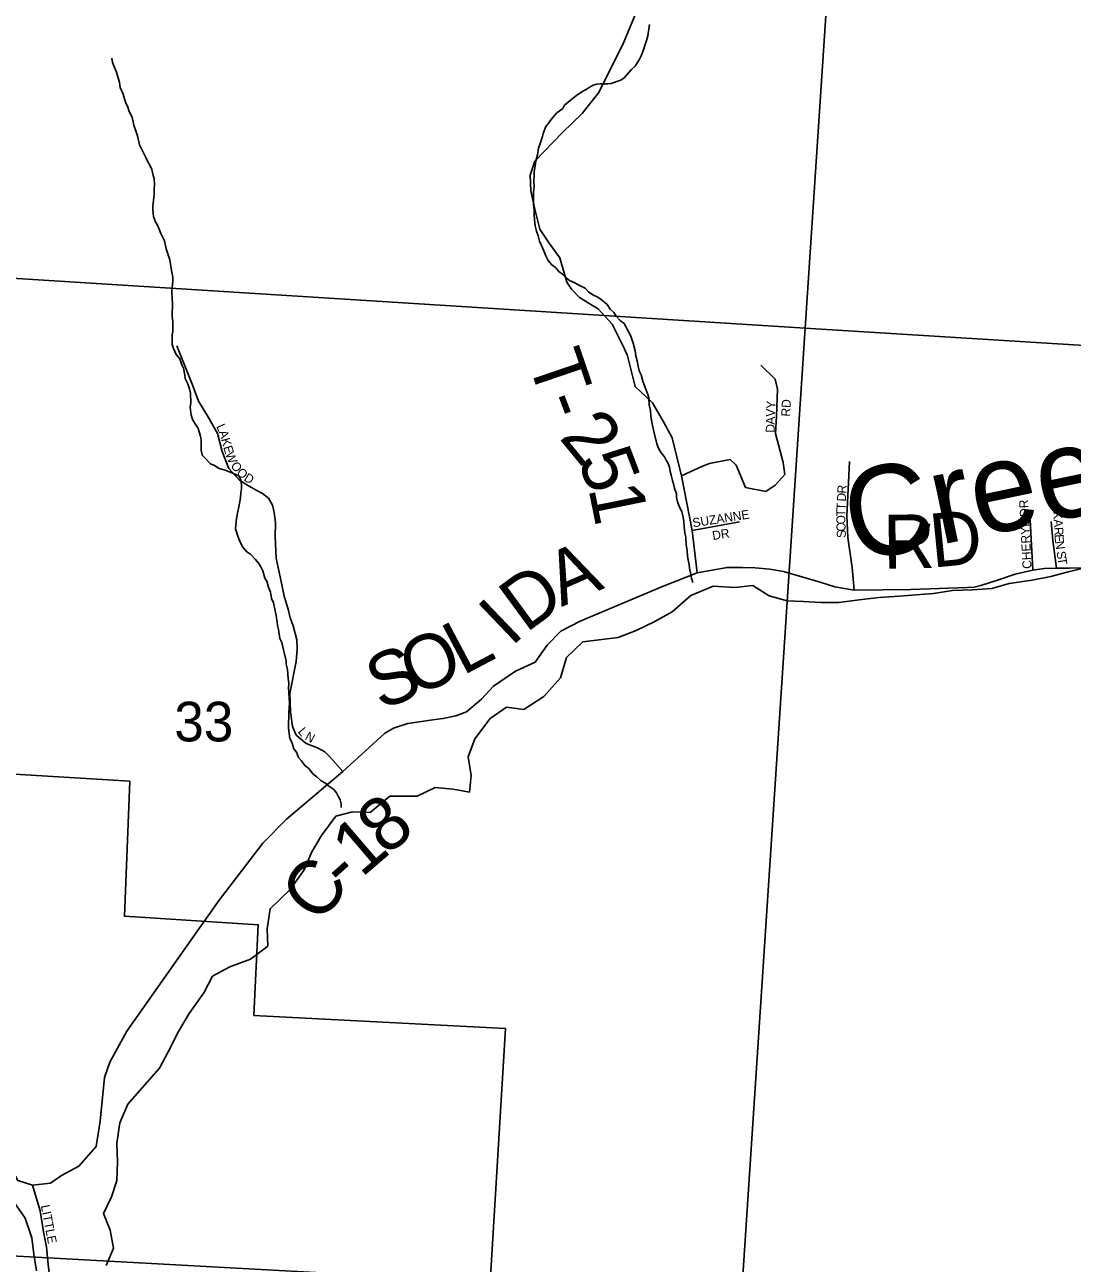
# Model space of a CAD drawing. Extents: x 1949938.81 to 1949945.61, y 152207.65 to 152214.09.
# Drawn here: x 1949941.599 to 1949942.704, y 152209.158 to 152210.465 of the extents above; entities that cross this region are included whole.
import ezdxf

# ---------------------------------------------------------------- set-up
doc = ezdxf.new("R2010")
doc.units = 0
for name, color, linetype in [('GM_X_City_Street', 7, 'Continuous'), ('GM_X_City_Street_Text', 7, 'Continuous'), ('GM_X_Corporation', 7, 'Continuous'), ('GM_X_County_Road', 7, 'Continuous'), ('GM_X_County_Road_Text', 7, 'Continuous'), ('GM_X_Minor_River', 7, 'Continuous'), ('GM_X_Minor_River_Text', 7, 'Continuous'), ('GM_X_Section', 7, 'Continuous'), ('GM_X_Section_Text', 7, 'Continuous'), ('GM_X_Township_Road', 7, 'Continuous'), ('GM_X_Township_Road_Text', 7, 'Continuous'), ('GM_X_Township_Subdivision', 7, 'Continuous'), ('GM_X_Township_Subdivision_Text', 7, 'Continuous')]:
    doc.layers.add(name, color=color, linetype=linetype)

msp = doc.modelspace()

# ---------------------------------------------------------------- linework, layer by layer
at = {"layer": 'GM_X_City_Street'}
for points in [[(1949941.4126, 152209.4825), (1949941.4273, 152209.4684), (1949941.4548, 152209.436), (1949941.4824, 152209.4065), (1949941.4928, 152209.3941), (1949941.4976, 152209.3871), (1949941.5005, 152209.3722), (1949941.5121, 152209.3585), (1949941.528, 152209.3455), (1949941.544, 152209.3266), (1949941.5648, 152209.2665), (1949941.5827, 152209.2632), (1949941.592, 152209.2455), (1949941.6075, 152209.2407), (1949941.6263, 152209.2428), (1949941.6379, 152209.251), (1949941.6564, 152209.2608), (1949941.6746, 152209.2817), (1949941.6788, 152209.3083), (1949941.6833, 152209.3542), (1949941.689, 152209.3706), (1949941.7068, 152209.4032), (1949941.7925, 152209.5244), (1949941.7945, 152209.5273)], [(1949941.6075, 152209.2407), (1949941.6156, 152209.2137), (1949941.6192, 152209.1915), (1949941.6221, 152209.1757), (1949941.6235, 152209.1607), (1949941.6257, 152209.142)]]:
    msp.add_lwpolyline(points, dxfattribs=at)
at = {"layer": 'GM_X_Corporation'}
msp.add_lwpolyline([(1949941.299, 152209.692), (1949941.7101, 152209.6669), (1949941.7046, 152209.5244), (1949941.8455, 152209.5155), (1949941.8409, 152209.4198), (1949942.1062, 152209.4059), (1949942.0896, 152209.1325)], dxfattribs=at)
at = {"layer": 'GM_X_County_Road'}
for points in [[(1949941.7945, 152209.5273), (1949941.8034, 152209.54), (1949941.8504, 152209.6014), (1949941.8754, 152209.627), (1949941.9347, 152209.6773), (1949941.9626, 152209.7025), (1949941.9788, 152209.7171), (1949941.988, 152209.723), (1949942.0032, 152209.7279), (1949942.0296, 152209.7315), (1949942.0403, 152209.733), (1949942.0537, 152209.7358), (1949942.0651, 152209.74), (1949942.0808, 152209.7534), (1949942.0936, 152209.7671), (1949942.1167, 152209.7831), (1949942.1376, 152209.7926), (1949942.1501, 152209.8104), (1949942.1645, 152209.8252), (1949942.1849, 152209.8359), (1949942.2719, 152209.8722), (1949942.3083, 152209.8869)], [(1949942.3083, 152209.8869), (1949942.3401, 152209.8924), (1949942.3561, 152209.8924), (1949942.3695, 152209.8921), (1949942.385, 152209.8906), (1949942.3995, 152209.888), (1949942.4381, 152209.877), (1949942.4536, 152209.8718), (1949942.474, 152209.8685), (1949942.5335, 152209.8691), (1949942.5934, 152209.8712), (1949942.6003, 152209.8716), (1949942.6073, 152209.8735), (1949942.6259, 152209.8795), (1949942.6437, 152209.8853), (1949942.6623, 152209.8896), (1949942.6747, 152209.8912), (1949942.6871, 152209.8918), (1949942.701, 152209.8916), (1949942.7151, 152209.8919)]]:
    msp.add_lwpolyline(points, dxfattribs=at)
at = {"layer": 'GM_X_Minor_River'}
for points in [[(1949942.1685, 152210.3801), (1949942.1743, 152210.385), (1949942.1812, 152210.3902), (1949942.1877, 152210.395), (1949942.1912, 152210.3965), (1949942.1946, 152210.3987), (1949942.1988, 152210.4013), (1949942.2022, 152210.4024), (1949942.2064, 152210.4027), (1949942.214, 152210.4025), (1949942.2178, 152210.4029), (1949942.2235, 152210.405), (1949942.2277, 152210.4065), (1949942.2315, 152210.4091), (1949942.2392, 152210.4177), (1949942.2431, 152210.4211), (1949942.2474, 152210.4286), (1949942.2493, 152210.432), (1949942.2517, 152210.4384), (1949942.2533, 152210.4429), (1949942.2553, 152210.4494), (1949942.2562, 152210.4532), (1949942.2579, 152210.4653)], [(1949941.7545, 152210.184), (1949941.7554, 152210.1943), (1949941.7555, 152210.1988), (1949941.7541, 152210.2057), (1949941.7524, 152210.2171), (1949941.751, 152210.2213), (1949941.7485, 152210.2286), (1949941.7467, 152210.237), (1949941.7427, 152210.2447), (1949941.7412, 152210.2493), (1949941.7394, 152210.2535), (1949941.7372, 152210.2569), (1949941.735, 152210.2627), (1949941.7344, 152210.2692), (1949941.7345, 152210.2737), (1949941.7358, 152210.2859), (1949941.7359, 152210.2923), (1949941.736, 152210.2958), (1949941.7357, 152210.3026), (1949941.7347, 152210.306), (1949941.7332, 152210.3122), (1949941.7307, 152210.3175), (1949941.7289, 152210.321), (1949941.727, 152210.3248), (1949941.7248, 152210.329), (1949941.7204, 152210.3382), (1949941.7183, 152210.3478), (1949941.7169, 152210.352), (1949941.7144, 152210.3589), (1949941.7126, 152210.3676), (1949941.7093, 152210.3734), (1949941.7079, 152210.378), (1949941.7057, 152210.3834), (1949941.7032, 152210.3918), (1949941.6999, 152210.3987), (1949941.6992, 152210.404), (1949941.696, 152210.4151), (1949941.6917, 152210.425), (1949941.691, 152210.4296)], [(1949942.3037, 152209.8766), (1949942.3022, 152209.8812), (1949942.3015, 152209.885), (1949942.3001, 152209.8915), (1949942.2998, 152209.8953), (1949942.2988, 152209.9003), (1949942.2981, 152209.9045), (1949942.2978, 152209.9102), (1949942.2968, 152209.9163), (1949942.2965, 152209.9243), (1949942.2955, 152209.9289), (1949942.2948, 152209.935), (1949942.2942, 152209.9414), (1949942.2932, 152209.9468), (1949942.2921, 152209.951), (1949942.2892, 152209.9571), (1949942.2877, 152209.9617), (1949942.2867, 152209.9663), (1949942.2864, 152209.9701), (1949942.2846, 152209.9762), (1949942.2835, 152209.9808), (1949942.2824, 152209.9842), (1949942.281, 152209.9899), (1949942.28, 152209.9938), (1949942.2793, 152209.9983), (1949942.2778, 152210.0022), (1949942.2756, 152210.0056), (1949942.2738, 152210.0091), (1949942.2705, 152210.0133), (1949942.2675, 152210.0183), (1949942.2657, 152210.0229), (1949942.2629, 152210.0344), (1949942.2611, 152210.042), (1949942.2601, 152210.0477), (1949942.2594, 152210.0523), (1949942.2591, 152210.058), (1949942.2577, 152210.0641), (1949942.2574, 152210.0713), (1949942.2564, 152210.0748), (1949942.2542, 152210.0805), (1949942.2524, 152210.0851), (1949942.2509, 152210.0889), (1949942.2492, 152210.0958), (1949942.2473, 152210.0997), (1949942.2459, 152210.1065), (1949942.2449, 152210.1103), (1949942.2435, 152210.1157), (1949942.2428, 152210.121), (1949942.2407, 152210.129), (1949942.2385, 152210.1363), (1949942.2352, 152210.1424), (1949942.2334, 152210.1459), (1949942.2312, 152210.1497), (1949942.2274, 152210.1525), (1949942.223, 152210.1575), (1949942.2204, 152210.1613), (1949942.2167, 152210.1648), (1949942.2133, 152210.1698), (1949942.207, 152210.1752), (1949942.2036, 152210.1776), (1949942.1984, 152210.18), (1949942.1939, 152210.1831), (1949942.1901, 152210.1869), (1949942.1834, 152210.1901), (1949942.1793, 152210.1928), (1949942.1736, 152210.1952), (1949942.1703, 152210.1979), (1949942.1665, 152210.2018), (1949942.1624, 152210.2045), (1949942.1591, 152210.2088), (1949942.155, 152210.2115), (1949942.1513, 152210.2161), (1949942.1487, 152210.2211), (1949942.1472, 152210.2246), (1949942.1454, 152210.2295), (1949942.1422, 152210.2368), (1949942.1407, 152210.2422), (1949942.1389, 152210.2471), (1949942.1375, 152210.2529), (1949942.1369, 152210.259), (1949942.1366, 152210.265), (1949942.1363, 152210.2689), (1949942.1356, 152210.2757), (1949942.1359, 152210.2883), (1949942.1363, 152210.2939), (1949942.1361, 152210.3008), (1949942.1365, 152210.3057), (1949942.1366, 152210.3103), (1949942.1375, 152210.3156), (1949942.1383, 152210.3213), (1949942.14, 152210.3277), (1949942.1412, 152210.3346), (1949942.1424, 152210.3387), (1949942.1452, 152210.347), (1949942.146, 152210.3504), (1949942.1488, 152210.3576), (1949942.1515, 152210.361), (1949942.1554, 152210.3663), (1949942.1604, 152210.3719), (1949942.1666, 152210.3767), (1949942.1685, 152210.3801)], [(1949941.9328, 152209.6392), (1949941.9329, 152209.643), (1949941.9319, 152209.6472), (1949941.93, 152209.6506), (1949941.9282, 152209.6545), (1949941.9252, 152209.658), (1949941.9211, 152209.6611), (1949941.9163, 152209.6649), (1949941.9117, 152209.6673), (1949941.9073, 152209.6716), (1949941.9035, 152209.6743), (1949941.8987, 152209.6804), (1949941.895, 152209.6832), (1949941.8909, 152209.6886), (1949941.8879, 152209.692), (1949941.8858, 152209.6974), (1949941.8832, 152209.7012), (1949941.881, 152209.7081), (1949941.8788, 152209.712), (1949941.8775, 152209.723), (1949941.8778, 152209.7397), (1949941.8782, 152209.7435), (1949941.8783, 152209.75), (1949941.878, 152209.7538), (1949941.8778, 152209.761), (1949941.8775, 152209.7652), (1949941.8776, 152209.7705), (1949941.8769, 152209.7751), (1949941.8763, 152209.7846), (1949941.8749, 152209.7903), (1949941.8749, 152209.7938), (1949941.8732, 152209.8014), (1949941.8721, 152209.8056), (1949941.8704, 152209.8132), (1949941.8682, 152209.8174), (1949941.8668, 152209.827), (1949941.8657, 152209.8312), (1949941.8654, 152209.8346), (1949941.8644, 152209.8418), (1949941.8634, 152209.8468), (1949941.8616, 152209.8552), (1949941.8594, 152209.8598), (1949941.8584, 152209.8663), (1949941.8562, 152209.8716), (1949941.8544, 152209.8778), (1949941.8526, 152209.8812), (1949941.8505, 152209.8888), (1949941.8483, 152209.8931), (1949941.8461, 152209.8965), (1949941.8424, 152209.9011), (1949941.8375, 152209.9066), (1949941.8334, 152209.9089), (1949941.8293, 152209.9139), (1949941.826, 152209.9197), (1949941.8235, 152209.9266), (1949941.8217, 152209.9331), (1949941.8218, 152209.9369), (1949941.8226, 152209.9441), (1949941.8239, 152209.9513), (1949941.8251, 152209.9562), (1949941.8256, 152209.96), (1949941.8268, 152209.966), (1949941.8273, 152209.971), (1949941.8277, 152209.9755), (1949941.8278, 152209.9801), (1949941.8271, 152209.9847), (1949941.8249, 152209.9889), (1949941.8178, 152209.9924), (1949941.8107, 152209.9952), (1949941.8042, 152209.9968), (1949941.7994, 152210), (1949941.7952, 152210.0019), (1949941.7897, 152210.0077), (1949941.7863, 152210.0108), (1949941.7853, 152210.0162), (1949941.7855, 152210.0268), (1949941.7848, 152210.031), (1949941.7823, 152210.039), (1949941.7797, 152210.0429), (1949941.7764, 152210.0479), (1949941.7749, 152210.0532), (1949941.7739, 152210.0616), (1949941.7744, 152210.0662), (1949941.7742, 152210.0764), (1949941.7731, 152210.0807), (1949941.7713, 152210.086), (1949941.7684, 152210.0918), (1949941.7681, 152210.0952), (1949941.7667, 152210.1028), (1949941.7649, 152210.1063), (1949941.7627, 152210.1124), (1949941.759, 152210.117), (1949941.7561, 152210.1235), (1949941.7546, 152210.1277), (1949941.7548, 152210.1376), (1949941.7553, 152210.1422), (1949941.7554, 152210.1517), (1949941.7548, 152210.1574), (1949941.755, 152210.1711), (1949941.7547, 152210.1756), (1949941.7545, 152210.184)], [(1949941.6971, 152209.2655), (1949941.6965, 152209.2852), (1949941.6996, 152209.3065), (1949941.708, 152209.3262), (1949941.7232, 152209.3436), (1949941.7415, 152209.3641), (1949941.7506, 152209.3815), (1949941.7613, 152209.4028), (1949941.7728, 152209.4217), (1949941.788, 152209.4437), (1949941.7972, 152209.4612), (1949941.8154, 152209.471), (1949941.8374, 152209.4793), (1949941.8556, 152209.4929), (1949941.8549, 152209.5111), (1949941.858, 152209.5324), (1949941.8793, 152209.5528), (1949941.8938, 152209.5733), (1949941.9022, 152209.5923), (1949941.9121, 152209.6097), (1949941.9274, 152209.6302), (1949941.9448, 152209.6347), (1949941.9637, 152209.6338), (1949941.9843, 152209.6512), (1949942.013, 152209.6511), (1949942.032, 152209.6602), (1949942.0509, 152209.6586), (1949942.0684, 152209.6555), (1949942.0699, 152209.673), (1949942.067, 152209.6928), (1949942.0739, 152209.7117), (1949942.0899, 152209.733), (1949942.1073, 152209.7451), (1949942.1255, 152209.7427), (1949942.1468, 152209.7563), (1949942.1643, 152209.776), (1949942.1704, 152209.7973), (1949942.1879, 152209.8139), (1949942.225, 152209.8184), (1949942.244, 152209.8259), (1949942.263, 152209.835), (1949942.282, 152209.8455), (1949942.3017, 152209.8629), (1949942.3252, 152209.8727), (1949942.348, 152209.8711), (1949942.3669, 152209.8733), (1949942.3843, 152209.8626), (1949942.4032, 152209.8573), (1949942.4206, 152209.8564), (1949942.4388, 152209.8556), (1949942.4577, 152209.8555), (1949942.482, 152209.8585), (1949942.5002, 152209.8607), (1949942.5214, 152209.8621), (1949942.5577, 152209.8651), (1949942.5774, 152209.868), (1949942.5987, 152209.8687), (1949942.6191, 152209.8701), (1949942.6373, 152209.8754), (1949942.6616, 152209.8791), (1949942.6813, 152209.8828), (1949942.701, 152209.8881), (1949942.723, 152209.8933)], [(1949941.6853, 152209.1561), (1949941.693, 152209.1743), (1949941.6893, 152209.1933), (1949941.6825, 152209.2108), (1949941.6909, 152209.2283), (1949941.6963, 152209.2457), (1949941.6971, 152209.2655)], [(1949941.5879, 152209.2233), (1949941.5999, 152209.2058), (1949941.6067, 152209.1852), (1949941.6089, 152209.1678), (1949941.6118, 152209.1503)]]:
    msp.add_lwpolyline(points, dxfattribs=at)
at = {"layer": 'GM_X_Section'}
for points in [[(1949942.4891, 152211.1555), (1949942.4221, 152210.1447), (1949941.3344, 152210.2133), (1949941.3926, 152211.2226)], [(1949943.6063, 152211.0859), (1949943.5439, 152210.0754), (1949942.4221, 152210.1447), (1949942.4891, 152211.1555)], [(1949941.3344, 152210.2133), (1949942.4221, 152210.1447), (1949942.3551, 152209.1241), (1949941.2772, 152209.1831)], [(1949942.4221, 152210.1447), (1949943.5439, 152210.0754), (1949943.4815, 152209.0627), (1949942.3551, 152209.1241)]]:
    msp.add_lwpolyline(points, close=True, dxfattribs=at)
at = {"layer": 'GM_X_Township_Road'}
for points in [[(1949942.2006, 152210.1673), (1949942.1981, 152210.1688), (1949942.1842, 152210.1772), (1949942.1759, 152210.1859), (1949942.1709, 152210.1935), (1949942.1637, 152210.219), (1949942.1524, 152210.2346), (1949942.1425, 152210.2494), (1949942.1372, 152210.2703), (1949942.1331, 152210.2897), (1949942.1323, 152210.3064), (1949942.1372, 152210.3209), (1949942.1664, 152210.3512), (1949942.1869, 152210.3714), (1949942.2043, 152210.393), (1949942.23, 152210.444), (1949942.2516, 152210.4968), (1949942.2607, 152210.515), (1949942.2657, 152210.5485), (1949942.2814, 152210.6236)], [(1949942.2329, 152210.1204), (1949942.2316, 152210.1231), (1949942.2187, 152210.149), (1949942.2039, 152210.1654), (1949942.2006, 152210.1673)], [(1949942.2774, 152210.0375), (1949942.2727, 152210.0462), (1949942.2613, 152210.066), (1949942.2429, 152210.0833), (1949942.2346, 152210.1171), (1949942.2329, 152210.1204)], [(1949942.3083, 152209.8869), (1949942.303, 152209.9314), (1949942.2919, 152209.9889), (1949942.2819, 152210.0291), (1949942.2774, 152210.0375)]]:
    msp.add_lwpolyline(points, dxfattribs=at)
at = {"layer": 'GM_X_Township_Subdivision'}
for points in [[(1949941.8734, 152209.8601), (1949941.8732, 152209.8605), (1949941.8696, 152209.8777), (1949941.8644, 152209.9021), (1949941.8633, 152209.9246), (1949941.8638, 152209.9397), (1949941.8623, 152209.9504), (1949941.8607, 152209.958), (1949941.8562, 152209.9656), (1949941.8501, 152209.9705), (1949941.844, 152209.9735), (1949941.8353, 152209.9785), (1949941.8258, 152209.9846), (1949941.8144, 152209.9967), (1949941.8076, 152210.0146), (1949941.8026, 152210.0336), (1949941.792, 152210.0522), (1949941.7824, 152210.068), (1949941.7766, 152210.0841), (1949941.7598, 152210.1262)], [(1949942.325, 152210.0028), (1949942.3376, 152210.0054), (1949942.3433, 152210.0063), (1949942.3494, 152210.0002), (1949942.3593, 152209.9767), (1949942.3808, 152209.9724), (1949942.3907, 152209.9791), (1949942.4007, 152209.9905), (1949942.3989, 152210.003), (1949942.3911, 152210.0339), (1949942.392, 152210.0521), (1949942.3929, 152210.0806), (1949942.3907, 152210.0909), (1949942.3753, 152210.1059)], [(1949942.2919, 152209.9889), (1949942.3138, 152209.9991), (1949942.3215, 152210.0021), (1949942.325, 152210.0028)], [(1949942.474, 152209.8685), (1949942.4719, 152209.8924), (1949942.4673, 152209.9239), (1949942.4661, 152209.9471), (1949942.4678, 152209.9821), (1949942.4691, 152210.0041)], [(1949942.303, 152209.9314), (1949942.353, 152209.9406)], [(1949942.6623, 152209.8896), (1949942.6593, 152209.9428)], [(1949942.6871, 152209.8918), (1949942.6835, 152209.9209), (1949942.6816, 152209.9409)], [(1949941.9347, 152209.6773), (1949941.9211, 152209.6927), (1949941.9157, 152209.6979), (1949941.908, 152209.702), (1949941.8962, 152209.7068), (1949941.8856, 152209.7156), (1949941.8815, 152209.7248), (1949941.8795, 152209.74), (1949941.879, 152209.7595), (1949941.8854, 152209.7933), (1949941.8867, 152209.8061), (1949941.8862, 152209.8159), (1949941.8824, 152209.8307), (1949941.8791, 152209.8392), (1949941.8774, 152209.847), (1949941.8734, 152209.8601)]]:
    msp.add_lwpolyline(points, dxfattribs=at)

# ---------------------------------------------------------------- texts
at = {"layer": 'GM_X_City_Street_Text'}
msp.add_text('LITTLE', height=0.00947, rotation=280.8384, dxfattribs=at).set_placement((1949941.6162, 152209.2191))
at = {"layer": 'GM_X_County_Road_Text'}
for s, rotation, p in [('D', 5.6492, (1949942.5564, 152209.8921)), ('R', 0.8443, (1949942.5047, 152209.8911)), ('A', 23.6227, (1949942.1652, 152209.8506)), ('D', 36.2524, (1949942.1277, 152209.8227)), ('I', 43.7313, (1949942.1124, 152209.8078)), ('O', 23.0796, (1949942.0103, 152209.7561)), ('L', 27.9642, (1949942.061, 152209.7779)), ('S', 22.9889, (1949941.9749, 152209.7411)), ('8', 40.3495, (1949941.9808, 152209.5872)), ('1', 40.6202, (1949941.9543, 152209.5644)), ('C', 50.205, (1949941.9088, 152209.5148)), ('-', 41.8567, (1949941.9371, 152209.5491))]:
    msp.add_text(s, height=0.0568, rotation=rotation, dxfattribs=at).set_placement(p)
at = {"layer": 'GM_X_Minor_River_Text'}
msp.add_text('Creek', height=0.0947, rotation=11.8017, dxfattribs=at).set_placement((1949942.4743, 152209.8973))
at = {"layer": 'GM_X_Section_Text'}
msp.add_text('33', height=0.04186, rotation=0, dxfattribs=at).set_placement((1949941.757, 152209.7089))
at = {"layer": 'GM_X_Township_Road_Text'}
for s, rotation, p in [('T', 288.8339, (1949942.1294, 152210.1105)), ('-', 290.6471, (1949942.1438, 152210.0684)), ('2', 309.2786, (1949942.162, 152210.0292)), ('5', 290.818, (1949942.1818, 152210.0063)), ('1', 281.4519, (1949942.1935, 152209.976))]:
    msp.add_text(s, height=0.0568, rotation=rotation, dxfattribs=at).set_placement(p)
at = {"layer": 'GM_X_Township_Subdivision_Text'}
for s, rotation, p in [('V', 87.7044, (1949942.3902, 152210.0512)), ('Y', 87.0043, (1949942.3906, 152210.0595)), ('RD', 87.1392, (1949942.4063, 152210.0514)), ('L', 294.45, (1949941.801, 152210.0413)), ('A', 89.6503, (1949942.3902, 152210.043)), ('A', 287.952, (1949941.8037, 152210.0355)), ('D', 89.9563, (1949942.3902, 152210.0346)), ('K', 284.8536, (1949941.8062, 152210.0277)), ('E', 287.2066, (1949941.8085, 152210.0193)), ('W', 291.0246, (1949941.8106, 152210.0123)), ('O', 306.658, (1949941.8159, 152209.9997)), ('O', 316.1942, (1949941.822, 152209.9917)), ('D', 327.5983, (1949941.8296, 152209.9847)), ('R', 87.1331, (1949942.4655, 152209.9702)), ('D', 87.1355, (1949942.4651, 152209.9618)), ('SUZANNE', 8.8802, (1949942.3042, 152209.9347)), ('T', 88.5518, (1949942.4645, 152209.9461)), ('T', 87.2396, (1949942.4646, 152209.9527)), ('CHERYL DR', 92.9341, (1949942.661, 152209.8912)), ('O', 91.5083, (1949942.4647, 152209.9379)), ('K', 273.1489, (1949942.6837, 152209.9514)), ('A', 273.1489, (1949942.6842, 152209.9431)), ('DR', 8.974, (1949942.325, 152209.9213)), ('C', 91.9918, (1949942.4649, 152209.9304)), ('S', 91.9948, (1949942.4652, 152209.9237)), ('R', 273.1344, (1949942.6847, 152209.9348)), ('E', 274.2654, (1949942.6851, 152209.9271)), ('N', 277.8822, (1949942.6856, 152209.9198)), ('S', 278.6102, (1949942.6872, 152209.9089)), ('T', 278.6145, (1949942.6882, 152209.9023)), ('L', 309.684, (1949941.8867, 152209.7189)), ('N', 331.5598, (1949941.894, 152209.7113))]:
    msp.add_text(s, height=0.00947, rotation=rotation, dxfattribs=at).set_placement(p)

doc.saveas('drawing.dxf')
